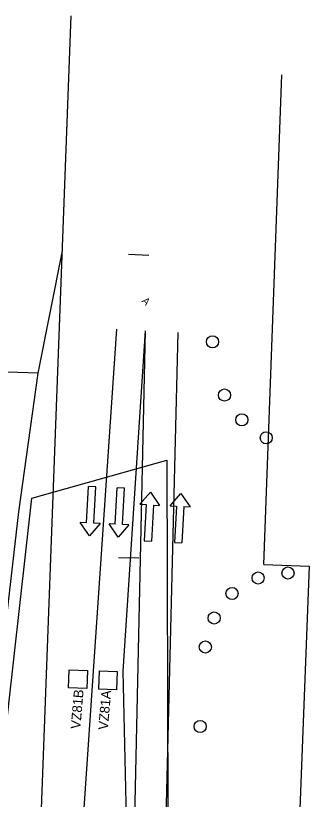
# Model space of a CAD drawing. Extents: x 679444 to 687671, y 733868 to 736107.
# Drawn here: x 680949.5 to 681046.4, y 735359.2 to 735617.8 of the extents above; entities that cross this region are included whole.
import ezdxf

# ---------------------------------------------------------------- set-up
doc = ezdxf.new("R2010")
doc.units = 0
for name, color, linetype in [('$', 7, 'Continuous'), ('090338 Base_Design base 1-1 - R_Horz Alg', 7, 'Continuous'), ('Clipping Boundary', 7, 'Continuous'), ('MOT Stage 1', 7, 'Continuous'), ('MOT Stage 1 Lanes', 7, 'Continuous'), ('R_Horz Alg Station', 7, 'Continuous'), ('RW-EX', 7, 'Continuous'), ('RW-PR', 7, 'Continuous'), ('Video-Zones-pr', 7, 'Continuous')]:
    doc.layers.add(name, color=color, linetype=linetype)

# ---------------------------------------------------------------- blocks, each defined once
blk = doc.blocks.new('BAREL_1519')
at = {"layer": 'MOT Stage 1'}
blk.add_circle((0, 0.01), 2.88, dxfattribs=at)
blk = doc.blocks.new('BAREL_1555')
at = {"layer": 'MOT Stage 1'}
blk.add_circle((0, 0.01), 2.88, dxfattribs=at)
blk = doc.blocks.new('BAREL_1556')
at = {"layer": 'MOT Stage 1'}
blk.add_circle((0, 0.01), 2.88, dxfattribs=at)
blk = doc.blocks.new('BAREL_1557')
at = {"layer": 'MOT Stage 1'}
blk.add_circle((0, 0.01), 2.88, dxfattribs=at)
blk = doc.blocks.new('BAREL_1558')
at = {"layer": 'MOT Stage 1'}
blk.add_circle((0, 0.01), 2.88, dxfattribs=at)
blk = doc.blocks.new('BAREL_1559')
at = {"layer": 'MOT Stage 1'}
blk.add_circle((0, 0.01), 2.88, dxfattribs=at)
blk = doc.blocks.new('BAREL_1560')
at = {"layer": 'MOT Stage 1'}
blk.add_circle((0, 0.01), 2.88, dxfattribs=at)
blk = doc.blocks.new('BAREL_1561')
at = {"layer": 'MOT Stage 1'}
blk.add_circle((0, 0.01), 2.88, dxfattribs=at)
blk = doc.blocks.new('BAREL_1562')
at = {"layer": 'MOT Stage 1'}
blk.add_circle((0, 0.01), 2.88, dxfattribs=at)
blk = doc.blocks.new('BAREL_1563')
at = {"layer": 'MOT Stage 1'}
blk.add_circle((0, 0.01), 2.88, dxfattribs=at)
blk = doc.blocks.new('SARROW_178')
at = {"layer": 'MOT Stage 1'}
for p, q in [((-6, -29.42), (-6, 0)), ((0, 0), (-6, 0)), ((0, -29.42), (0, 0)), ((-6, -29.42), (-11, -29.42)), ((-3, -39.81), (-11, -29.42)), ((5, -29.42), (-3, -39.81)), ((5, -29.42), (0, -29.42))]:
    blk.add_line(p, q, dxfattribs=at)
blk = doc.blocks.new('SARROW_179')
at = {"layer": 'MOT Stage 1'}
for p, q in [((0, 0), (-6, 0)), ((0, -29.42), (0, 0)), ((-6, -29.42), (-6, 0)), ((-6, -29.42), (-11, -29.42)), ((-3, -39.81), (-11, -29.42)), ((5, -29.42), (-3, -39.81)), ((5, -29.42), (0, -29.42))]:
    blk.add_line(p, q, dxfattribs=at)
blk = doc.blocks.new('SARROW_181')
at = {"layer": 'MOT Stage 1'}
for p, q in [((0, 0), (-6, 0)), ((0, -29.42), (0, 0)), ((-6, -29.42), (-6, 0)), ((-6, -29.42), (-11, -29.42)), ((-3, -39.81), (-11, -29.42)), ((5, -29.42), (-3, -39.81)), ((5, -29.42), (0, -29.42))]:
    blk.add_line(p, q, dxfattribs=at)
blk = doc.blocks.new('SARROW_184')
at = {"layer": 'MOT Stage 1'}
for p, q in [((-6, -29.42), (-6, 0)), ((0, 0), (-6, 0)), ((0, -29.42), (0, 0)), ((-6, -29.42), (-11, -29.42)), ((-3, -39.81), (-11, -29.42)), ((5, -29.42), (-3, -39.81)), ((5, -29.42), (0, -29.42))]:
    blk.add_line(p, q, dxfattribs=at)

msp = doc.modelspace()

# ---------------------------------------------------------------- linework, layer by layer
at = {"layer": 'Clipping Boundary'}
msp.add_lwpolyline([(680983.49, 735238.92), (680930.7, 735241.61), (680945.08, 735370.96), (680954.81, 735458.55), (680999.35, 735471.11), (681000.07, 735239.64)], close=True, dxfattribs=at)
at = {"layer": 'MOT Stage 1 Lanes'}
for p, q in [((680967.48, 735289.6), (680982.89, 735514.32)), ((680984.91, 735401.49), (680992.34, 735513.78)), ((680987.46, 735288.81), (680992.34, 735513.78)), ((681002.99, 735513.22), (680997.45, 735288.41)), ((680987.46, 735288.81), (680984.91, 735401.49))]:
    msp.add_line(p, q, dxfattribs=at)
at = {"layer": 'R_Horz Alg Station'}
for points in [[(680986.75, 735539.09), (680993.41, 735538.76)], [(680983.45, 735439.01), (680990.12, 735438.81)]]:
    msp.add_lwpolyline(points, dxfattribs=at)
at = {"layer": 'RW-EX'}
for p, q in [((680961.67, 735453.52), (680967.84, 735617.79)), ((680952.9, 735220.48), (680961.67, 735453.52)), ((681031.32, 735436.64), (681046.38, 735436.08)), ((681046.38, 735436.08), (681038.61, 735236.76))]:
    msp.add_line(p, q, dxfattribs=at)
msp.add_lwpolyline([(681031.32, 735436.64), (681037.29, 735598.24)], dxfattribs=at)
at = {"layer": 'RW-PR'}
msp.add_line((680956.91, 735499.83), (680936.92, 735500.42), dxfattribs=at)
msp.add_lwpolyline([(680926.04, 735241.19), (680950.55, 735454.08), (680956.91, 735499.83), (680964.93, 735540.2)], dxfattribs=at)
at = {"layer": 'Video-Zones-pr'}
for points in [[(680972.92, 735395.69), (680966.92, 735395.93), (680967.16, 735401.92), (680973.16, 735401.69)], [(680973.16, 735401.69), (680972.92, 735395.69)], [(680977.04, 735401.53), (680976.8, 735395.54)], [(680977.04, 735401.53), (680983.03, 735401.3), (680982.8, 735395.3), (680976.8, 735395.54)]]:
    msp.add_lwpolyline(points, dxfattribs=at)

# ---------------------------------------------------------------- block references
at = {"layer": 'MOT Stage 1'}
for name, p, xscale, yscale, rotation in [('BAREL_1519', (681014.45, 735510.16), 0.6945420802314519, 0.6945420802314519, 87.04179557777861), ('BAREL_1563', (681018.38, 735492.58), 0.6945420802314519, 0.6945420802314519, 87.04179557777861), ('BAREL_1562', (681024.11, 735484.39), 0.6945420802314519, 0.6945420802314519, 87.04179557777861), ('BAREL_1561', (681032.18, 735478.47), 0.6945420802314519, 0.6945420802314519, 87.04179557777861), ('SARROW_179', (680975.94, 735462.26), 0.4075873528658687, 0.4075873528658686, -3.081123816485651), ('SARROW_181', (680985.42, 735461.8), 0.4075873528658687, 0.4075873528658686, -3.081123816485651), ('SARROW_178', (680991.85, 735444.45), 0.4075873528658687, 0.4075873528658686, 176.91887618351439), ('SARROW_184', (681001.9, 735443.96), 0.4075873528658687, 0.4075873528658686, 176.91887618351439), ('BAREL_1559', (681029.48, 735432.21), 0.6945420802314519, 0.6945420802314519, 87.04179557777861), ('BAREL_1560', (681039.35, 735433.84), 0.6945420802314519, 0.6945420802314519, 87.04179557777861), ('BAREL_1558', (681020.89, 735427.09), 0.6945420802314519, 0.6945420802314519, 87.04179557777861), ('BAREL_1557', (681015.01, 735419), 0.6945420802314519, 0.6945420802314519, 87.04179557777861), ('BAREL_1556', (681012.08, 735409.44), 0.6945420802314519, 0.6945420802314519, 87.04179557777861), ('BAREL_1555', (681010.36, 735383.17), 0.6945420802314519, 0.6945420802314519, 87.04179557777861)]:
    msp.add_blockref(name, p, dxfattribs=dict(at, xscale=xscale, yscale=yscale, rotation=rotation))

# ---------------------------------------------------------------- texts
at = {"layer": '$'}
for s, p in [('VZ81B', (680970.8, 735382.25)), ('VZ81A', (680979.89, 735381.97))]:
    msp.add_text(s, height=3.2, rotation=85.0338, dxfattribs=at).set_placement(p)
at = {"layer": '090338 Base_Design base 1-1 - R_Horz Alg'}
msp.add_text('A', height=2.4, rotation=315.2103, dxfattribs=at).set_placement((680990.94, 735523.46))

doc.saveas('drawing.dxf')
